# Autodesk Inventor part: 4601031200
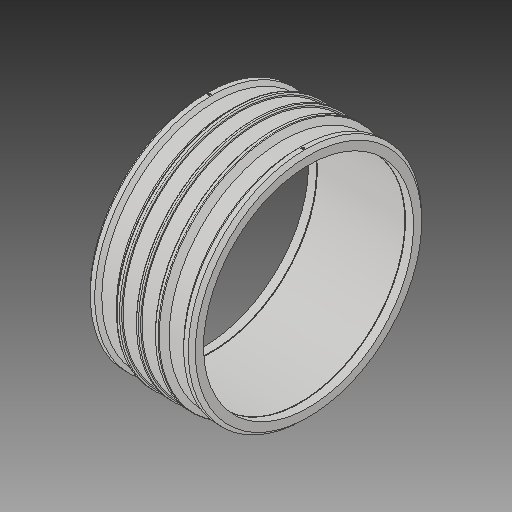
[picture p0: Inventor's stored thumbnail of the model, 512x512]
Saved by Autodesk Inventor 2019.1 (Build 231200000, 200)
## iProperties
Created: 2017-06
Part Number: 4601031200
Material: Generic
Description: PLASSON LIGHTFIT COUPLER 1200
Document SubType Name: Modeling
Designer: KIM
Mass: 17859.4 g
Surface Area: 15499.5 cm^2
Volume: 17859.4 cm^3
Density: 1 g/cm^3
Appearance: Default
Author: KIM
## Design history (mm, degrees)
derived "460103.ipt"
feature "Solid1::460103.ipt"
tag "TaggingFeature1"
body "Solid1"
other parameters: "d14" = 17.6296, "d19" = 3.52592, "d20" = 168 deg, "d22" = 1334, "d23" = 1355, "d24" = 1293.98, "d25" = 135 deg, "d27" = 135 deg, "d29" = 667, "d35" = 15, "d39" = 0, "d40" = 4, "d41" = 14, "d42" = 0, "d43" = 135 deg, "d44" = 66, "d45" = 24, "d46" = 24, "d47" = 24, "d48" = 1327.9, "d49" = 1355, "d50" = 6.775, "d51" = 6, "d52" = 0, "D_" = 1355, "A_" = 667, "d_2" = 12
